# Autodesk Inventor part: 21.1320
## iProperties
Created: 2006-12
Part Number: 21.1320
Document SubType Name: Modeling
Designer: Andy Moles
Material: Steel, Mild
Density: 7.86 g/cm^3
Mass: 5.31606 g
Surface Area: 5.644 cm^2
Volume: 0.676344 cm^3
Description: M5 SQUARE NUT
Vendor: S
Author: Andy Moles
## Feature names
1. Extrusion1
2. Revolution1
